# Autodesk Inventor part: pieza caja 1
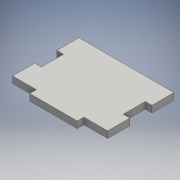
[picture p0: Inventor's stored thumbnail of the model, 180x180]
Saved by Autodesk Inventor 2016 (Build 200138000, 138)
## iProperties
Created: 2016-06
Part Number: pieza caja 1
Material: Genérico
Document SubType Name: Modeling
Designer: adm
Density: 1 g/cm^3
Appearance: Valor por defecto
Author: adm
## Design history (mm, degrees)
sketch "Boceto1"
  geometry: L1 (-10.75, -15.262)-(10.75, -15.262); L2 (21.5, -12.262)-(21.5, -2.262); L3 (21.5, 17.738)-(-21.5, 17.738); L4 (-21.5, -17.738)-(21.5, 17.738); L5 (21.5, -17.738)-(-21.5, 17.738); L6 (10.75, -12.262)-(10.75, -15.262); L7 (-10.75, -12.262)-(-10.75, -15.262); L8 (21.5, -12.262)-(10.75, -12.262); L9 (-10.75, -12.262)-(-21.5, -12.262); L10 (18.331, 3.113)-(18.5, 3.113); L11 (-21.5, -2.262)-(-18.5, -2.262); L12 (-21.5, 7.738)-(-18.5, 7.738); L13 (18.5, 7.738)-(21.5, 7.738); L14 (18.5, -2.262)-(21.5, -2.262); L15 (-18.5, 7.738)-(-18.5, -2.262); L16 (18.5, 7.738)-(18.5, -2.262); L17 (-21.5, 17.738)-(-21.5, 7.738); L18 (-21.5, -2.262)-(-21.5, -12.262); L19 (21.5, 17.738)-(21.5, 7.738); 1 further point
  constraints: 38 end point, 6 parallel, 3 point on line, 2 horizontal, 2 midpoint, 2 vertical, 1 perpendicular
  dimensions: "d13" = 43 distance of L3.start L3.end; "d14" = 30 distance between parallel lines of L9 L3; "d15" = 30 distance between parallel lines of L8 L3; "d16" = 3 distance between parallel lines of L1 L8; "d17" = 10 distance of L3.start L13.end; "d18" = 10 distance of L3.end L12.start; "d19" = 10 distance of L11.start L9.end; "d20" = 10 distance of L2.start L2.end; "d21" = 3 distance between parallel lines of L15 L17; "d22" = 3 distance between parallel lines of L16 L19; "d23" = 3 distance between parallel lines of L15 L18; "d24" = 3 distance between parallel lines of L16 L2; "d25" = 3 distance of L13.start L13.end; "d26" = 3 distance of L14.start L2.end
extrude "Extrusión1" new body sketch "Boceto1" distance "d11" = 3; taper "d12" = 0 deg
node "Sólido1"
other parameters: "d10" = 3
